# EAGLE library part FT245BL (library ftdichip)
USB FIFO 2nd Generation USB FIFO (USB <-> Parallel) Controller
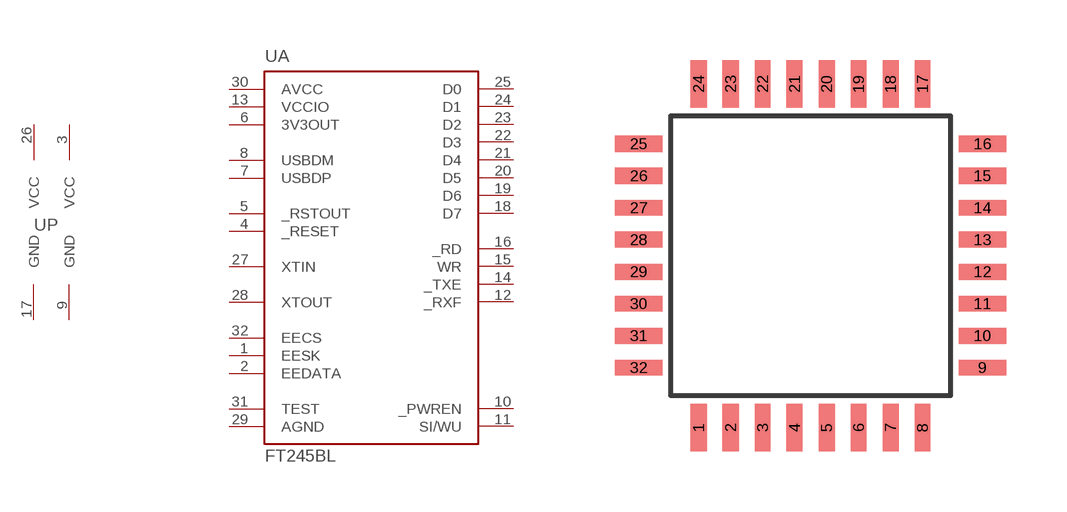
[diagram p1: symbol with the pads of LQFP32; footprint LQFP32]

Designator prefix U; gates A=FT245BL P=2VCC2GND

## FT245BL  [LQFP32]
1  A:EESK  out
2  A:EEDATA
3  P:VCC  pwr
4  A:_RESET  in
5  A:_RSTOUT  out
6  A:3V3OUT  out
7  A:USBDP
8  A:USBDM
9  P:GND  pwr
10  A:_PWREN  out
11  A:SI/WU  in
12  A:_RXF  out
13  A:VCCIO  pwr
14  A:_TXE  out
15  A:WR  in
16  A:_RD  in
17  P:GND  pwr
18  A:D7
19  A:D6
20  A:D5
21  A:D4
22  A:D3
23  A:D2
24  A:D1
25  A:D0
26  P:VCC  pwr
27  A:XTIN  in
28  A:XTOUT  out
29  A:AGND  pwr
30  A:AVCC  pwr
31  A:TEST  in
32  A:EECS

## Footprint LQFP32 (pad centres in mm)
LQFP-32 package 7x7 mm case, 0.8 mm lead pitch
smd 0.4 x 1.2: 1 -2.8,-4.3; 2 -2,-4.3; 3 -1.2,-4.3; 4 -0.4,-4.3; 5 0.4,-4.3; 6 1.2,-4.3; 7 2,-4.3; 8 2.8,-4.3; 17 2.8,4.3; 18 2,4.3; 19 1.2,4.3; 20 0.4,4.3; 21 -0.4,4.3; 22 -1.2,4.3; 23 -2,4.3; 24 -2.8,4.3
smd 1.2 x 0.4: 9 4.3,-2.8; 10 4.3,-2; 11 4.3,-1.2; 12 4.3,-0.4; 13 4.3,0.4; 14 4.3,1.2; 15 4.3,2; 16 4.3,2.8; 25 -4.3,2.8; 26 -4.3,2; 27 -4.3,1.2; 28 -4.3,0.4; 29 -4.3,-0.4; 30 -4.3,-1.2; 31 -4.3,-2; 32 -4.3,-2.8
